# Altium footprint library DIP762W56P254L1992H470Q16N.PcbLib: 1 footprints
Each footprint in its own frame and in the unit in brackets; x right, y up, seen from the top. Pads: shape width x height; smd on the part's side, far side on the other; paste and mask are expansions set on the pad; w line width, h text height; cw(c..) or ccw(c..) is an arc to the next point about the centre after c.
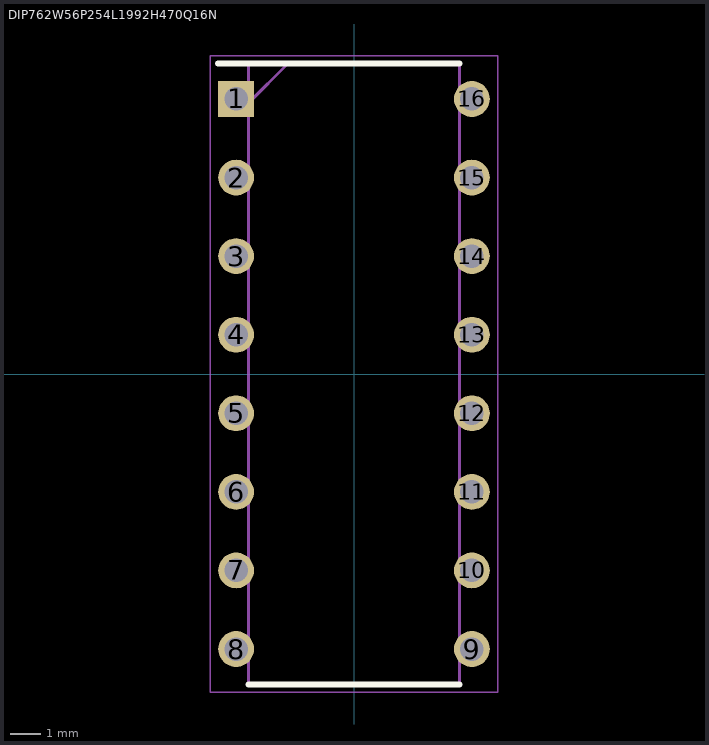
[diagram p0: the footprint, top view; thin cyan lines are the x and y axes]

## DIP762W56P254L1992H470Q16N [mm]
pads (16):
  rect 1.16x1.16 / inner round 1.16 / far side rect 1.16x1.16 hole 0.76: 1(-3.81,8.89)
  round 1.16 hole 0.76: 2(-3.81,6.35) 3(-3.81,3.81) 4(-3.81,1.27) 5(-3.81,-1.27) 6(-3.81,-3.81) 7(-3.81,-6.35) 8(-3.81,-8.89) 9(3.81,-8.89) 10(3.81,-6.35) 11(3.81,-3.81) 12(3.81,-1.27) 13(3.81,1.27) 14(3.81,3.81) 15(3.81,6.35) 16(3.81,8.89)
Top Overlay:
  lines w0.2: -4.39,10.035 3.405,10.035 ; -3.405,-10.035 3.405,-10.035
Mechanical 15:
  lines w0.1: -3.405,8.765 -2.135,10.035 ; -3.405,-10.035 3.405,-10.035 3.405,10.035 -3.405,10.035 -3.405,-10.035
Mechanical 20:
  lines w0.05: -4.64,-10.285 4.64,-10.285 4.64,10.285 -4.64,10.285 -4.64,-10.285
